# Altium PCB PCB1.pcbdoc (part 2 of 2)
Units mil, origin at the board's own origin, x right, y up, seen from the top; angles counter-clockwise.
Board outline 3937 x 1574.8 mil, 4 copper layers (Top Layer, Inner1, Inner2, Bottom Layer), stack 62.3 mil thick; 79 components, 49 nets, 279 pads, 327 vias.
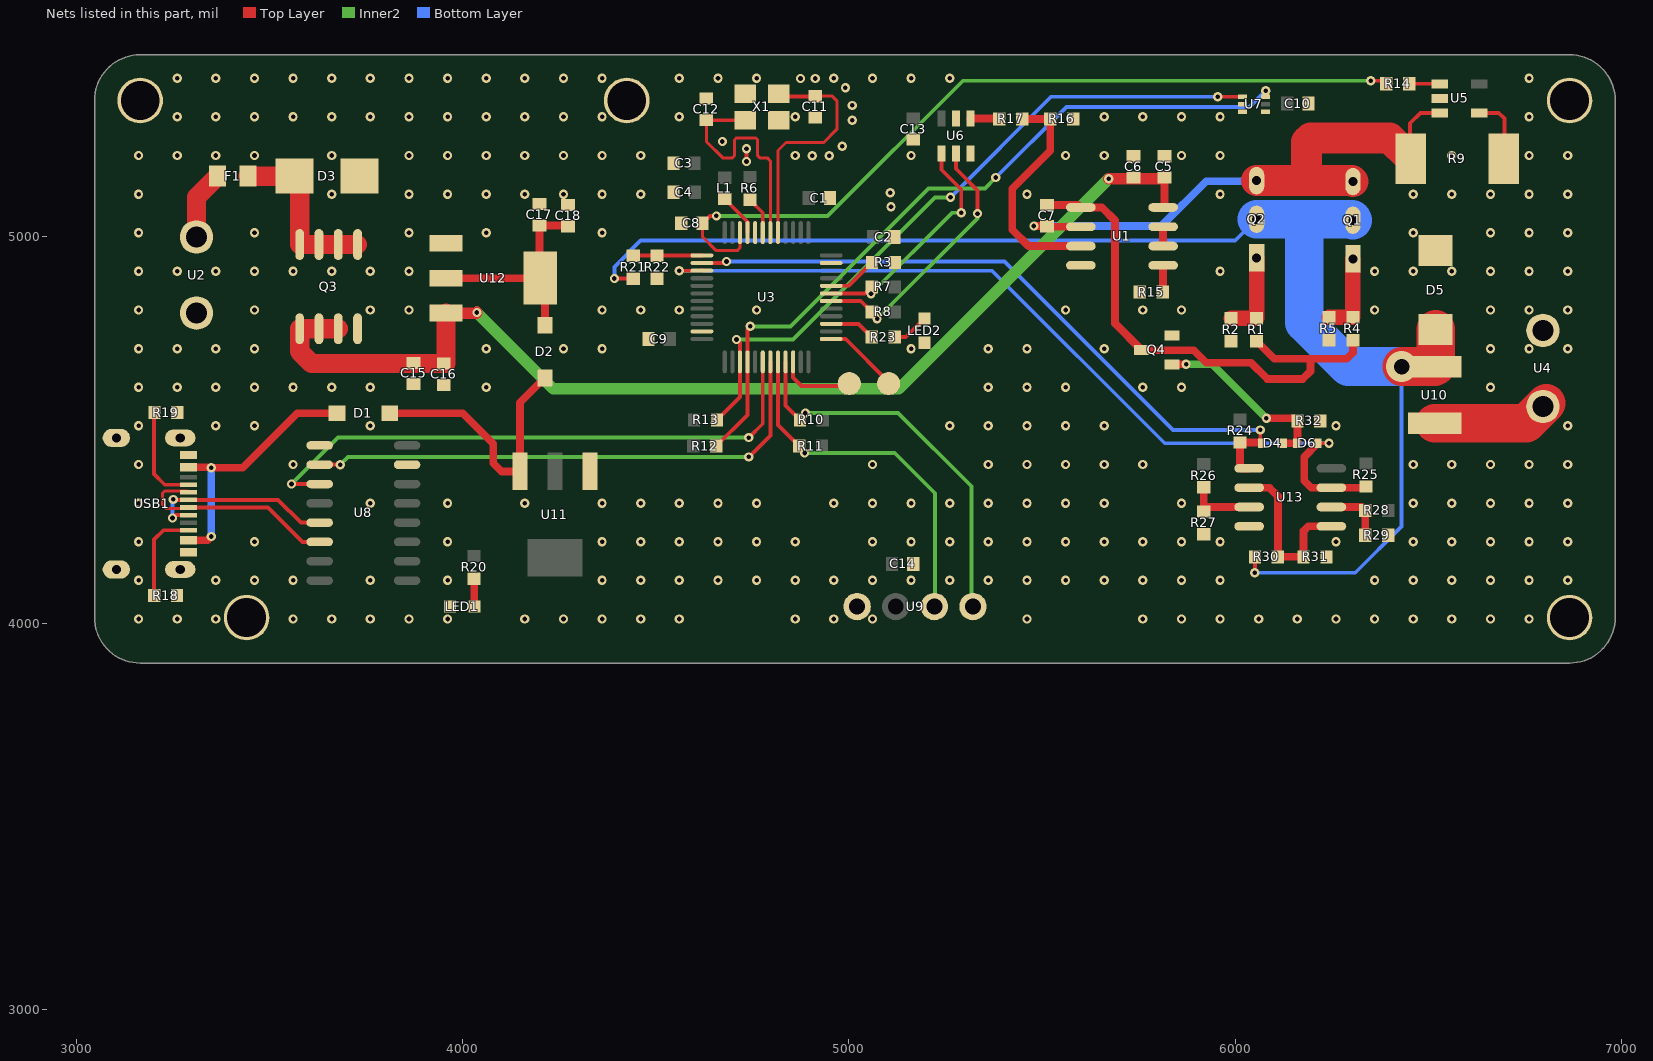
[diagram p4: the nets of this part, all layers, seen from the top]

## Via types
v1: diameter 24, hole 12, Top Layer to Bottom Layer, 326 vias
v2: diameter 80, hole 40, Top Layer to Bottom Layer, 1 vias

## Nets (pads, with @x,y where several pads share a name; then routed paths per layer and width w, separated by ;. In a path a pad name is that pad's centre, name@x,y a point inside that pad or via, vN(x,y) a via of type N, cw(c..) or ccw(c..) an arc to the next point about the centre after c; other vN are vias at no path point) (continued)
$1N126: L1.2 U3.9 | length 111.3
  Top Layer w10: L1.2@4678.6,5097.9 4737.5,5039 U3.9@4737.5,5011
$1N164: R6.2 U3.7 | length 98.6
  Top Layer w10: R6.2@4743.6,5095.8 4776.9,5062.5 U3.7@4776.9,5011
$1N212: R15.2 U1.5 | length 69.4
  Top Layer w20: R15.2@5812.5,4857.1 5813.4,4858 U1.5@5813.4,4926.1
$1N219: Q1.1 R4.2 R5.1 | length 213.2
  Top Layer w40: R5.1@6242.9,4791.9 R4.2@6304.9,4791.9 Q1.1@6304.9,4943.1
$1N221: Q2.1 R1.2 R2.1 | length 222.3
  Top Layer w40: R2.1@5989.6,4789.2 R1.2@6055.6,4789.2 Q2.1@6055.6,4945.5
$1N267: R14.2 U5.1 | length 79.4
  Top Layer w10: R14.2@6450.5,5396.2 6529.1,5396.2 U5.1@6529.7,5395.6
$1N317: C17.2 C18.2 D2.2 U12.2 U12.4 | length 582.8
  Top Layer w20: U12.2@3956.9,4893.1 U12.4@4200.9,4893.1 ; D2.2@4212.9,4771.4 4212.9,4881.1 U12.4@4200.9,4893.1 ; C18.2@4272.9,5027.6 4270.9,5029.6 C17.2@4198.9,5029.6 4198.9,4895.1 U12.4@4200.9,4893.1
$1N320: LED1.2 R20.2 | length 71.9
  Top Layer w20: R20.2@4029.8,4114.6 4029.8,4043.5 LED1.2@4030.4,4042.9
$1N345: R23.1 U3.39 | length 119
  Top Layer w10: U3.39@4954.1,4774.7 5024.7,4774.7 R23.1@5058.9,4740.5
$1N346: LED2.2 R23.2 | length 97.6
  Top Layer w10: R23.2@5118.3,4740.5 5147.3,4740.5 LED2.2@5195.8,4789
$1N390: R28.1 R29.1 U13.6 | length 155.6
  Top Layer w20: U13.6@6249.2,4300.5 6328.1,4300.5 R28.1@6337.1,4291.5 R29.1@6337.1,4227.5
$1N398: R26.2 R27.2 U13.3 | length 184.9
  Top Layer w20: R26.2@5918.7,4351.8 R27.2@5918.7,4289.1 5930.1,4300.5 U13.3@6036.2,4300.5
+5V: D1.1 D2.1 U11.3 | length 698
  Top Layer w20: D1.1@3811.2,4543.1 4000,4543.1 4078.9,4464.2 4078.9,4414.2 4100.9,4392.2 4147.8,4392.2 U11.3@4148.3,4392.7 4148.3,4570.3 D2.1@4212.9,4634.8
+12V: C5.2 C6.2 C15.2 C16.2 Q3.1 Q3.2 Q3.3 U1.8 U12.3 | length 2929.6
  Top Layer w20: U1.8@5813.4,5076.1 5816.9,5079.6 C5.2@5816.9,5153.6
  Top Layer w30: U12.3@3956.9,4802.6 4035.2,4802.6 v1(4036.9,4804.2) ; v1(5672.9,5150.2) 5813.5,5150.2 C5.2@5816.9,5153.6
  Top Layer w50: Q3.3@3677.9,4762.2 Q3.2@3627.9,4762.2 Q3.1@3577.9,4762.2 3577.9,4703.2 3608.9,4672.2 3956.9,4672.2 U12.3@3956.9,4802.6
  Inner2 w30: v1(4036.9,4804.2) 4234.9,4606.2 5128.9,4606.2 v1(5672.9,5150.2)
ADC: C8.2 R14.1 U3.10 | length 2115.6
  Top Layer w8: C8.2@4620.9,5035.2 4620.9,5000.2 4656.9,4964.2 4710.9,4964.2 4717.8,4971.2 U3.10@4717.8,5011
  Top Layer w10: C8.2@4621.1,5035.5 4639.9,5054.2 v1(4656.9,5054.2) ; v1(6350.9,5404.2) 6383.2,5404.2 R14.1@6391.2,5396.2
  Inner2 w10: v1(4656.9,5054.2) 4944.9,5054.2 5294.9,5404.2 v1(6350.9,5404.2)
BOOT0: R3.1 U3.44 | length 131
  Top Layer w10: U3.44@4954.1,4873.2 4999,4873.2 R3.1@5059.9,4934
DAC_OUT: R17.1 U6.1 | length 75.5
  Top Layer w20: U6.1@5314.3,5306.4 5388,5306.4 R17.1@5389.2,5305.1
FAULT_KILL: D4.2 D6.2 Q4.1 R32.2 | length 479.5
  Top Layer w20: Q4.1@5836.3,4669.7 5836.7,4670.2 v1(5872.9,4670.2) ; v1(6080.9,4530.2) 6154.3,4530.2 R32.2@6161.1,4523.5 6161.1,4467.4 D6.2@6159.2,4465.5 D4.2@6124.3,4465.5
  Inner2 w20: v1(5872.9,4670.2) 5940.9,4670.2 v1(6080.9,4530.2)
GATE_CTRL: C7.2 Q4.3 R1.1 R4.1 U1.1 | length 1373.3
  Top Layer w20: C7.2@5512.9,5082.7 5593.8,5082.7 U1.1@5600.4,5076.1 5600.5,5076.2 5654.9,5076.2 5688.9,5042.2 5688.9,4775.8 Q4.3@5757.5,4707.1 5758.4,4706.2 5892.9,4706.2 5924.9,4674.2 6040.9,4674.2 6082.9,4632.2 6174.9,4632.2 6194.9,4652.2 6194.9,4681.6 6192.3,4684.2 ; R1.1@6055.6,4729.8 6101.2,4684.2 6192.3,4684.2 ; R4.1@6304.9,4732.6 6304.9,4700.2 6288.9,4684.2 6192.3,4684.2
GND: C1.2 C2.2 C3.1 C4.1 C5.1 C6.1 C8.1 C9.2 C10.1 C11.2 C12.1 C13.1 C14.2 C15.1 C16.1 C17.1 C18.1 D3.2 D5.2 LED1.1 LED2.1 pad.1@3165,5352.9 pad.1@3440.6,4014.3 pad.1@4424.8,5352.9 pad.1@6865.8,4014.3 pad.1@6865.8,5352.9 Q3.4 Q4.2 R2.2 R3.2 R5.2 R9.2 R15.1 R16.2 R18.1 R19.1 R22.2 R27.1 R29.2 R31.2 R32.1 U1.4 U2.2 U3.8 U3.23 U3.47 U4.2 U5.2 U5.4 U6.2 U6.6 U7.2 U7.3 U7.4 U8.1 U8.15 U9.1 U11.1 U12.1 U13.4 USB1.13 USB1.14 USB1.A1B12 USB1.B1A12 X1.2 X1.4 | length 208.6
  Top Layer w10: v1(4734.9,5195) v1(4734.9,5228.2) ; U5.4@6632.1,5320.8 6682.3,5320.8 6696.9,5306.2 6696.9,5203.5 R9.2@6695.6,5202.2
  other v1: 3161,4010.6 3261,4010.6 3361,4010.6 3561,4010.6 3661,4010.6 3761,4010.6 3861,4010.6 3961,4010.6 4161,4010.6 4261,4010.6 4361,4010.6 4461,4010.6 4561,4010.6 4861,4010.6 4961,4010.6 5061,4010.6 5461,4010.6 5761,4010.6 5861,4010.6 5961,4010.6 6061,4010.6 6161,4010.6 6261,4010.6 6361,4010.6 6461,4010.6 6561,4010.6 6661,4010.6 6761,4010.6 3161,4110.6 3361,4110.6 3461,4110.6 3561,4110.6 3761,4110.6 3961,4110.6 4361,4110.6 4461,4110.6 4561,4110.6 4661,4110.6 4761,4110.6 4861,4110.6 4961,4110.6 5061,4110.6 5161,4110.6 5261,4110.6 5361,4110.6 5461,4110.6 5561,4110.6 5661,4110.6 5761,4110.6 5861,4110.6 5961,4110.6 6361,4110.6 6461,4110.6 6561,4110.6 6661,4110.6 6761,4110.6 6861,4110.6 3161,4210.6 3461,4210.6 3961,4210.6 4361,4210.6 4461,4210.6 4561,4210.6 4661,4210.6 4761,4210.6 4861,4210.6 5061,4210.6 5161,4210.6 5261,4210.6 5361,4210.6 5461,4210.6 5561,4210.6 5661,4210.6 5761,4210.6 5861,4210.6 5961,4210.6 6261,4210.6 6461,4210.6 6561,4210.6 6661,4210.6 6761,4210.6 6861,4210.6 3161,4310.6 3761,4310.6 3961,4310.6 4161,4310.6 4361,4310.6 4461,4310.6 4561,4310.6 4661,4310.6 4761,4310.6 4961,4310.6 5061,4310.6 5161,4310.6 5261,4310.6 5361,4310.6 5461,4310.6 5561,4310.6 5661,4310.6 5861,4310.6 6461,4310.6 6561,4310.6 6661,4310.6 6761,4310.6 6861,4310.6 3161,4410.6 3561,4410.6 5061,4410.6 5361,4410.6 5461,4410.6 5561,4410.6 5661,4410.6 5761,4410.6 6461,4410.6 6561,4410.6 6661,4410.6 6761,4410.6 6861,4410.6 3161,4510.6 3361,4510.6 3461,4510.6 3761,4510.6 5261,4510.6 5361,4510.6 5461,4510.6 5561,4510.6 5661,4510.6 6261,4510.6 6861,4510.6 3161,4610.6 3261,4610.6 3361,4610.6 3461,4610.6 3561,4610.6 3661,4610.6 3761,4610.6 4061,4610.6 5361,4610.6 5461,4610.6 5561,4610.6 5761,4610.6 5861,4610.6 6661,4610.6 3161,4710.6 3261,4710.6 3361,4710.6 3461,4710.6 4061,4710.6 4261,4710.6 4361,4710.6 5161,4710.6 5361,4710.6 5461,4710.6 5661,4710.6 6661,4710.6 6761,4710.6 6861,4710.6 3161,4810.6 3461,4810.6 3761,4810.6 3861,4810.6 4361,4810.6 4461,4810.6 4561,4810.6 4761,4810.6 5561,4810.6 5761,4810.6 5861,4810.6 6361,4810.6 6661,4810.6 6761,4810.6 6861,4810.6 3161,4910.6 3261,4910.6 3361,4910.6 3461,4910.6 3561,4910.6 3661,4910.6 3761,4910.6 3861,4910.6 5961,4910.6 6361,4910.6 6461,4910.6 6561,4910.6 6661,4910.6 6761,4910.6 6861,4910.6 3161,5010.6 3461,5010.6 3861,5010.6 4061,5010.6 4361,5010.6 6461,5010.6 6661,5010.6 6761,5010.6 6861,5010.6 5108.9,5078.2 3161,5110.6 3661,5110.6 3861,5110.6 3961,5110.6 4061,5110.6 4161,5110.6 4261,5110.6 4361,5110.6 4461,5110.6 5461,5110.6 5961,5110.6 6461,5110.6 6561,5110.6 6661,5110.6 6761,5110.6 6861,5110.6 5106.9,5114.2 4904.9,5210.2 4949,5210.2 3161,5210.6 3261,5210.6 3361,5210.6 3461,5210.6 3661,5210.6 3861,5210.6 3961,5210.6 4061,5210.6 4161,5210.6 4261,5210.6 4361,5210.6 4461,5210.6 4861,5210.6 5161,5210.6 5561,5210.6 5661,5210.6 5861,5210.6 5961,5210.6 6561,5210.6 6761,5210.6 6861,5210.6 4982.9,5234.2 4672.5,5246.7 5008.9,5302.2 3261,5310.6 3361,5310.6 3461,5310.6 3561,5310.6 3661,5310.6 3761,5310.6 3861,5310.6 3961,5310.6 4061,5310.6 4161,5310.6 4261,5310.6 4361,5310.6 4561,5310.6 4861,5310.6 5661,5310.6 5761,5310.6 5861,5310.6 5961,5310.6 6761,5310.6 5008.9,5340.3 4990.9,5386.2 4874.8,5409.8 4912.9,5409.8 3261,5410.6 3361,5410.6 3461,5410.6 3561,5410.6 3661,5410.6 3761,5410.6 3861,5410.6 3961,5410.6 4061,5410.6 4161,5410.6 4261,5410.6 4361,5410.6 4561,5410.6 4661,5410.6 4761,5410.6 4961,5410.6 5061,5410.6 5161,5410.6 5261,5410.6 6761,5410.6
I2C1_SCL: R8.1 U3.42 U6.5 | length 675.5
  Top Layer w10: U3.42@4954.1,4833.8 5030.6,4833.8 R8.1@5058.9,4805.5 ; U6.5@5276.9,5215.9 5276.9,5176.2 5332.9,5120.2 v1(5332.9,5060.2)
  Inner2 w10: v1(5073,4787.8) 5332.9,5047.6 v1(5332.9,5060.2)
I2C1_SDA: R7.1 U3.43 U6.4 | length 607.2
  Top Layer w10: U3.43@4954.1,4853.5 5041.9,4853.5 R7.1@5058.9,4870.5 ; U6.4@5239.5,5215.9 5239.5,5173.6 5290.9,5122.2 v1(5290.9,5062.2)
  Inner2 w10: v1(5057.3,4852.8) 5266.7,5062.2 v1(5290.9,5062.2)
I2C2_SCL: R11.1 U3.32 U9.3 | length 915.7
  Top Layer w10: U3.32@4816.3,4676.3 4816.3,4513.2 R11.1@4871.2,4458.2
  Inner2 w10: v1(4885.3,4440.5) 5118.6,4440.5 5222.9,4336.2 5222.9,4044.5 U9.3@5221.2,4042.8
I2C2_SDA: R10.1 U3.33 U9.4 | length 986.8
  Top Layer w10: U3.33@4836,4676.3 4836,4563.5 R10.1@4873.2,4526.2
  Inner2 w10: v1(4887.3,4543.9) 5127.2,4543.9 5316.9,4354.2 5316.9,4047.1 U9.4@5321.2,4042.8
I_SET: R16.1 R17.2 U1.3 | length 595.2
  Top Layer w20: R17.2@5448.5,5305.1 R16.1@5521.2,5305.1 5521.2,5222.6 5422.9,5124.2 5422.9,5018.2 5464.9,4976.2 5600.3,4976.2 U1.3@5600.4,4976.1
ISENSE: C7.1 Q1.3 Q2.3 R9.1 U1.2 U5.3 | length 1581.1
  Top Layer w10: R9.1@6452.9,5203.5 6452.9,5294.2 6479.5,5320.8 U5.3@6529.7,5320.8
  Top Layer w20: v1(5478.9,5028.2) 5512.2,5028.2 C7.1@5512.9,5027.6 5514.3,5026.1 U1.2@5600.4,5026.1
  Top Layer w80: Q2.3@6055.6,5145.5 6165.2,5145.5 ; Q1.3@6304.9,5143.1 6302.5,5145.5 6165.2,5145.5 ; R9.1@6454.2,5202.2 6452.9,5203.5 6400.2,5256.2 6194.9,5256.2 6184.9,5246.2 6184.9,5165.2 6165.2,5145.5
  Bottom Layer w20: v1(5478.9,5028.2) 5808.9,5028.2 5924.9,5144.2 6054.3,5144.2 Q2.3@6055.6,5145.5
LOAD+: D5.1 Q1.2 Q2.2 R21.1 R30.1 U10.2 | length 3665.5
  Top Layer w10: v1(4392.9,4892.2) 4441.2,4892.2 R21.1@4441.6,4891.8 ; v1(6050.9,4130.2) 6050.9,4171.3 R30.1@6051.1,4171.5
  Top Layer w100: v2(6430.9,4664.2) 6515.9,4664.2 U10.2@6516.9,4663.2 6518.9,4665.2 D5.1@6518.9,4760.2
  Bottom Layer w10: v1(4392.9,4892.2) 4392.9,4922.2 4460.9,4990.2 6000.3,4990.2 Q2.2@6055.6,5045.5 ; v1(6050.9,4130.2) 6310.9,4130.2 6430.9,4250.2 v2(6430.9,4664.2)
  Bottom Layer w100: Q2.2@6055.6,5045.5 6302.5,5045.5 Q1.2@6304.9,5043.1 ; 6178.9,5032.2 6178.9,4778.2 6292.9,4664.2 v2(6430.9,4664.2)
LOAD_CMP_SENSE: R30.2 R31.1 U13.2 U13.5 | length 451.6
  Top Layer w20: U13.2@6036.2,4350.5 6088.6,4350.5 6110.9,4328.2 6110.9,4172 R30.2@6110.4,4171.5 R31.1@6177.1,4171.5 6177.1,4238.4 6189.1,4250.5 U13.5@6249.2,4250.5
LOAD_IN+: U4.1 U10.1 | length 310.6
  Top Layer w100: U10.1@6516.9,4517.2 6753.4,4517.2 U4.1@6805.8,4569.6
LOAD_VOLT_ADC: R21.2 R22.1 U3.13 | length 178.1
  Top Layer w10: R21.2@4441.6,4951.1 4442.4,4951.9 U3.13@4619.4,4951.9
OP2_BUF_OUT: U1.6 U1.7 | length 50
  Top Layer w20: U1.6@5813.4,4976.1 U1.7@5813.4,5026.1
OSC_IN: C11.1 U3.5 X1.3 | length 620.5
  Top Layer w8: U3.5@4816.3,5011 4816.3,5223.6 4836.9,5244.2 4934.9,5244.2 4968.9,5278.2 4968.9,5352.2 4956.9,5364.2 4913.3,5364.2 C11.1@4912.9,5363.8
  Top Layer w10: X1.3@4818.2,5370.7 4825.1,5363.8 C11.1@4912.9,5363.8
OSC_OUT: C12.2 U3.6 X1.1 | length 619.3
  Top Layer w8: C12.2@4630.9,5302.7 4630.9,5246.7 4673,5204.5 4698,5204.5 4703.7,5210.2 4703.7,5250.6 4709.3,5256.2 4758,5256.2 4763.7,5250.6 4763.7,5210.2 4769.3,5204.5 4788.6,5204.5 4796.6,5196.5 U3.6@4796.6,5011
  Top Layer w10: C12.2@4630.9,5302.7 4631.8,5301.8 X1.1@4731.6,5301.8
OV_FAULT: D6.1 R25.1 U3.15 U13.7 | length 2235
  Top Layer w10: v1(4560.9,4912.2) 4619.1,4912.2 U3.15@4619.4,4912.5 ; D6.1@6214.3,4465.5 v1(6242.9,4465.5)
  Top Layer w20: D6.1@6214.3,4465.5 6178.9,4430.1 6178.9,4368.2 6196.9,4350.2 6249,4350.2 U13.7@6249.2,4350.5 6335.4,4350.5 R25.1@6338.7,4353.8
  Bottom Layer w10: v1(4560.9,4912.2) 5370.9,4912.2 5817.6,4465.5 v1(6242.9,4465.5)
REV_FAULT: D4.1 R24.1 U3.14 U13.1 | length 1804.2
  Top Layer w10: U3.14@4619.4,4932.2 4678.9,4932.2 v1(4682.9,4936.2) ; D4.1@6064.9,4469.7 v1(6064.9,4500.2)
  Top Layer w20: U13.1@6036.2,4400.5 6016.6,4400.5 6012.7,4404.4 R24.1@6012.7,4467.8 6066.8,4467.8 D4.1@6069.2,4465.5
  Bottom Layer w10: v1(4682.9,4936.2) 5402.9,4936.2 5838.9,4500.2 v1(6064.9,4500.2)
SW_SCL: R13.1 U3.27 U7.1 | length 1806.7
  Top Layer w10: R13.1@4658.5,4526.2 4717.8,4585.5 U3.27@4717.8,4676.3 4717.8,4725.3 v1(4708.9,4734.2) ; v1(5954.9,5362.7) U7.1@6019,5362.7
  Inner2 w10: v1(4708.9,4734.2) 4854.9,4734.2 5222.9,5102.2 v1(5262.9,5102.2)
  Bottom Layer w10: v1(5262.9,5102.2) 5523.4,5362.7 v1(5954.9,5362.7)
SW_SDA: R12.1 U3.28 U7.6 | length 1949.1
  Top Layer w10: R12.1@4656.5,4458.2 4737.5,4539.2 U3.28@4737.5,4676.3 4737.5,4760.9 v1(4744.9,4768.2) ; U7.6@6078.1,5362.7 6078.9,5363.5 v1(6078.9,5378.2)
  Inner2 w10: v1(4744.9,4768.2) 4848.9,4768.2 5205.9,5125.2 5351.9,5125.2 v1(5380.3,5153.6)
  Bottom Layer w10: v1(5380.3,5153.6) 5562.9,5336.2 6036.9,5336.2 v1(6078.9,5378.2)
SWCLK: pad.1@5102.9,4620.2 U3.37 | length 198.9
  Top Layer w10: U3.37@4954.1,4735.4 4991.7,4735.4 5102.9,4624.2 pad.1@5102.9,4620.2
SWDIO: pad.1@5000.9,4620.2 U3.34 | length 197.4
  Top Layer w10: U3.34@4855.6,4676.3 4855.6,4635.5 4876.9,4614.2 4994.9,4614.2 pad.1@5000.9,4620.2
USART1_RX: U3.31 U8.2 | length 1388.6
  Top Layer w10: U8.2@3629.8,4410.1 3629.9,4410.2 v1(3682.9,4410.2) ; v1(4740.9,4430.2) 4796.6,4485.9 U3.31@4796.6,4676.3
  Inner2 w10: v1(3682.9,4410.2) 3702.9,4430.2 v1(4740.9,4430.2)
USART1_TX: U3.30 U8.3 | length 1517.7
  Top Layer w10: v1(3556.9,4360.2) 3629.7,4360.2 U8.3@3629.8,4360.1 ; v1(4740.9,4480.2) 4776.9,4516.2 U3.30@4776.9,4676.3
  Inner2 w10: v1(3556.9,4360.2) 3676.9,4480.2 v1(4740.9,4480.2)
USB_CC1: R19.2 USB1.A5 | length 260.4
  Top Layer w10: R19.2@3201.9,4545.1 3200.9,4544.1 3200.9,4386.2 3228.8,4358.3 USB1.A5@3290.4,4358.3
USB_CC2: R18.2 USB1.B5 | length 244.6
  Top Layer w10: R18.2@3201.2,4071.1 3200.9,4071.5 3200.9,4216.2 3224.9,4240.2 USB1.B5@3290.4,4240.2
USB_DN: U8.6 USB1.A7 USB1.B7 | length 550.7
  Top Layer w8: USB1.A7@3290.4,4299.3 3287.3,4296.2 3232.9,4296.2 3222.9,4306.2 3222.9,4336.2 3228.9,4342.2 3286.8,4342.2 USB1.B7@3290.4,4338.7
  Top Layer w10: USB1.A7@3290.4,4299.3 3495.8,4299.3 3585,4210.1 U8.6@3629.8,4210.1
USB_DP: U8.5 USB1.A6 USB1.B6 | length 497.2
  Top Layer w10: v1(3248.9,4272.2) 3256.3,4279.6 USB1.B6@3290.4,4279.6 ; v1(3250.9,4320.2) 3252.1,4319 USB1.A6@3290.4,4319 3522.1,4319 3581,4260.1 U8.5@3629.8,4260.1
  Bottom Layer w10: v1(3248.9,4272.2) 3248.9,4318.2 v1(3250.9,4320.2)
USB_VBUS: D1.2 USB1.A4B9 USB1.B4A9 | length 683.6
  Top Layer w20: USB1.B4A9@3290.4,4214.6 3339.3,4214.6 v1(3348.9,4224.2) ; USB1.A4B9@3290.4,4403.6 3347.5,4403.6 v1(3348.9,4402.2) 3430.9,4402.2 3571.8,4543.1 D1.2@3674.6,4543.1
  Bottom Layer w20: v1(3348.9,4224.2) v1(3348.9,4402.2)
VIN_12V_FUSED: D3.1 F1.2 Q3.5 Q3.6 Q3.7 Q3.8 | length 452.6
  Top Layer w50: F1.2@3444.3,5157.1 D3.1@3564.2,5157.1 3577.9,5143.5 Q3.8@3577.9,4980.1 Q3.7@3627.9,4980.1 Q3.6@3677.9,4980.1 Q3.5@3727.9,4980.1
VIN_12V_IN: F1.1 U2.1 | length 180.1
  Top Layer w50: U2.1@3310.9,4999.6 3310.9,5102.5 F1.1@3365.5,5157.1
pads on no net: U3.2 U3.3 U3.4 U3.11 U3.12 U3.16 U3.17 U3.18 U3.19 U3.20 U3.21 U3.22 U3.25 U3.26 U3.29 U3.35 U3.36 U3.38 U3.40 U3.41 U3.45 U3.46 U8.7 U8.8 U8.9 U8.10 U8.11 U8.12 U8.13 U8.14 USB1.A8 USB1.B8

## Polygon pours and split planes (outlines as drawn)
GND on Top Layer (solid, remove dead copper, pour order 2): 3165,5471.3 ccw(c3165,5353.2) 3046.9,5353.2 3046.9,4014.6 ccw(c3165,4014.6) 3165,3896.5 6865.8,3896.5 ccw(c6865.8,4014.6) 6983.9,4014.6 6983.9,5353.2 ccw(c6865.8,5353.2) 6865.8,5471.3
GND on Bottom Layer (solid, remove dead copper, pour order 2): 3165,5471.3 ccw(c3165,5353.2) 3046.9,5353.2 3046.9,4014.6 ccw(c3165,4014.6) 3165,3896.5 6865.8,3896.5 ccw(c6865.8,4014.6) 6983.9,4014.6 6983.9,5353.2 ccw(c6865.8,5353.2) 6865.8,5471.3
GND on Inner1 (solid, remove dead copper): 3165,5471.3 ccw(c3165,5353.2) 3046.9,5353.2 3046.9,4014.6 ccw(c3165,4014.6) 3165,3896.5 6865.8,3896.5 ccw(c6865.8,4014.6) 6983.9,4014.6 6983.9,5353.2 ccw(c6865.8,5353.2) 6865.8,5471.3
GND on Inner2 (solid, remove dead copper): 3165,5471.3 ccw(c3165,5353.2) 3046.9,5353.2 3046.9,4014.6 ccw(c3165,4014.6) 3165,3896.5 6865.8,3896.5 ccw(c6865.8,4014.6) 6983.9,4014.6 6983.9,5353.2 ccw(c6865.8,5353.2) 6865.8,5471.3

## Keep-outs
Board Outline Layer:
  lines w10: 6865.8,3896.5 3165,3896.5 cw(c3165,4014.6) 3046.9,4014.6 3046.9,5353.2 cw(c3165,5353.2) 3165,5471.3 6865.8,5471.3 ; 6865.8,3896.5 6865.8,3896.5 ; 6865.8,3896.5 ccw(c6865.8,4014.6) 6983.9,4014.6 ; 6865.8,5471.3 cw(c6865.8,5353.2) 6983.9,5353.2 ; 6865.8,5471.3 6865.8,5471.3 ; 6983.9,4014.6 6983.9,4014.6 ; 6983.9,4014.6 6983.9,5353.2 ; 6983.9,5353.2 6983.9,5353.2

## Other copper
Top Layer:
  drawing of 259 lines, arcs and shapes, not listed
Inner2:
  region net I2C2_SCL: 5217.9,4092.3 5227.9,4089.8 5228.1,4087.9 5228.6,4086 5229.5,4084.2 5230.6,4082.4 5231.9,4080.6 5233.5,4078.9 5236.9,4075.5 5240.4,4072.4 5243.9,4069.6 5246.8,4067.1 5248.9,4065 5195.8,4067.5 5203.9,4076 5211,4083.8 5216,4089.6 5217.4,4091.4
  region net I2C2_SDA: 5311.9,4087.6 5321.9,4094.1 5322,4093.6 5322.4,4092.8 5323.8,4090.7 5326.1,4087.9 5329,4084.6 5336.3,4077.1 5344.7,4069.3 5292,4062.8 5293.9,4065 5296.6,4067.5 5303.3,4073.5 5306.5,4076.8 5308,4078.5 5309.3,4080.3 5310.4,4082.1 5311.2,4083.9 5311.7,4085.8
  region net USART1_TX: 4724.5,4475.2 4724.5,4485.2 4726.3,4485.6 4728.6,4486.5 4730.9,4487.8 4732.9,4489.2 4732.9,4471.2 4730.9,4472.7 4728.6,4474 4726.3,4474.9
  region net USART1_RX: 4724.5,4425.2 4724.5,4435.2 4726.3,4435.6 4728.6,4436.5 4730.9,4437.8 4732.9,4439.2 4732.9,4421.2 4730.9,4422.7 4728.6,4424 4726.3,4424.9
  region net 3V3: 4881.6,5137.4 4881.6,5157.4 4883.8,5157.5 4885.9,5157.7 4889.9,5158.4 4893.4,5159.1 4896,5159.4 4896,5135.4 4893.4,5135.7 4889.9,5136.4 4885.9,5137.1 4883.8,5137.3
  region net 3V3: 4618.1,5223.1 4604,5209 4602.4,5210.4 4600.8,5211.8 4597.4,5214.1 4594.5,5216.1 4592.4,5217.7 4609.4,5234.7 4611,5232.6 4613,5229.7 4615.3,5226.3 4616.7,5224.7
  region net USART1_TX: 3564.9,4375.3 3572,4368.2 3570.9,4366.7 3570,4364.5 3569.2,4361.9 3568.9,4359.5 3556.1,4372.2 3558.6,4372.6 3561.1,4373.3 3563.4,4374.3
  region net USART1_RX: 3690.9,4425.3 3698,4418.2 3696.9,4416.7 3696,4414.5 3695.2,4411.9 3694.9,4409.5 3682.1,4422.2 3684.6,4422.6 3687.1,4423.3 3689.4,4424.3
  region net 3V3: 6056.7,4594.2 6063.8,4601.3 6065.3,4600.3 6067.6,4599.3 6070.1,4598.6 6072.6,4598.2 6059.8,4585.5 6059.5,4587.9 6058.7,4590.5 6057.8,4592.7
  region net 3V3: 6086.2,4596.2 6086.2,4576.2 6084.1,4576.1 6082,4575.9 6078,4575.2 6074.5,4574.5 6071.8,4574.2 6071.8,4598.2 6074.5,4597.9 6078,4597.2 6082,4596.5 6084.1,4596.3
  region net 3V3: 6126.9,5291.1 6119.8,5298.2 6120.8,5299.7 6121.8,5302 6122.5,5304.5 6122.9,5307 6135.6,5294.2 6133.2,5293.9 6130.6,5293.1 6128.4,5292.2
  region net 3V3: 6151.2,5311.2 6151.2,5301.2 6149.4,5300.9 6147.2,5300 6144.8,5298.7 6142.8,5297.2 6142.8,5315.2 6144.8,5313.8 6147.2,5312.5 6149.4,5311.6
  region net 3V3: 6679.9,5377.9 6669.9,5377.9 6669.5,5379.7 6668.6,5381.9 6667.3,5384.3 6665.9,5386.3 6683.9,5386.3 6682.4,5384.3 6681.1,5381.9 6680.2,5379.7
  region net FAULT_KILL: 6063.6,4533.3 6077.8,4547.5 6079.4,4546 6081,4544.7 6084.3,4542.3 6087.3,4540.4 6089.4,4538.7 6072.4,4521.7 6070.7,4523.8 6068.8,4526.8 6066.4,4530.1 6065.1,4531.8
  region net FAULT_KILL: 5887.3,4680.2 5887.3,4660.2 5885.1,4660.1 5883,4659.9 5879,4659.2 5875.6,4658.5 5872.9,4658.2 5872.9,4682.2 5875.6,4681.9 5879,4681.2 5883,4680.5 5885.1,4680.3
  region net ADC: 4673.2,5059.2 4673.2,5049.2 4671.4,5048.9 4669.2,5048 4666.8,5046.7 4664.8,5045.2 4664.8,5063.2 4666.8,5061.8 4669.2,5060.5 4671.4,5059.6
  region net ADC: 6334.5,5399.2 6334.5,5409.2 6336.3,5409.6 6338.6,5410.5 6340.9,5411.8 6342.9,5413.2 6342.9,5395.2 6340.9,5396.7 6338.6,5398 6336.3,5398.9
  region net SW_SCL: 5246.5,5097.2 5246.5,5107.2 5248.3,5107.6 5250.6,5108.5 5252.9,5109.8 5254.9,5111.2 5254.9,5093.2 5252.9,5094.7 5250.6,5096 5248.3,5096.9
  region net SW_SCL: 4725.2,4739.2 4725.2,4729.2 4723.4,4728.9 4721.2,4728 4718.8,4726.7 4716.8,4725.2 4716.8,4743.2 4718.8,4741.8 4721.2,4740.5 4723.4,4739.6
  region net SW_SDA: 5372.3,5138.5 5365.2,5145.6 5366.2,5147.1 5367.2,5149.4 5367.9,5151.9 5368.3,5154.4 5381,5141.6 5378.6,5141.3 5376,5140.5 5373.8,5139.6
  region net SW_SDA: 4761.2,4773.2 4761.2,4763.2 4759.4,4762.9 4757.2,4762 4754.8,4760.7 4752.8,4759.2 4752.8,4777.2 4754.8,4775.8 4757.2,4774.5 4759.4,4773.6
  region net I2C1_SDA: 5065.3,4867.9 5072.4,4860.8 5071.4,4859.3 5070.4,4857 5069.6,4854.5 5069.3,4852 5056.5,4864.7 5059,4865.1 5061.5,4865.9 5063.8,4866.8
  region net I2C1_SCL: 5081.1,4802.9 5088.1,4795.8 5087.1,4794.3 5086.1,4792 5085.4,4789.5 5085,4787 5072.3,4799.7 5074.7,4800.1 5077.3,4800.9 5079.5,4801.8
  region net I2C1_SDA: 5274.5,5057.2 5274.5,5067.2 5276.3,5067.6 5278.6,5068.5 5280.9,5069.8 5282.9,5071.2 5282.9,5053.2 5280.9,5054.7 5278.6,5056 5276.3,5056.9
  region net I2C1_SCL: 5337.9,5047.6 5327.9,5047.6 5323.9,5052.3 5341.9,5052.3
  region net I2C2_SDA: 4903.7,4548.9 4903.7,4538.9 4901.9,4538.6 4899.6,4537.7 4897.3,4536.4 4895.3,4534.9 4895.3,4552.9 4897.3,4551.5 4899.6,4550.2 4901.9,4549.3
  region net I2C2_SCL: 4901.7,4445.5 4901.7,4435.5 4899.9,4435.2 4897.6,4434.3 4895.3,4433 4893.3,4431.5 4893.3,4449.5 4895.3,4448 4897.6,4446.8 4899.9,4445.8
  region net 3V3: 6328.9,4482.6 6348.9,4482.6 6349,4480.5 6349.2,4478.4 6349.9,4474.4 6350.6,4470.9 6350.9,4468.2 6326.9,4468.2 6327.2,4470.9 6327.9,4474.4 6328.6,4478.4 6328.8,4480.5
Bottom Layer:
  region net LOAD+: 6026.7,5009.6 6030.6,5027.6 6031.6,5028.8 6032.5,5030.4 6033.4,5032.4 6034.2,5034.5 6034.9,5036.8 6035.4,5039.1 6035.8,5041.4 6035.9,5043.5 6042.7,5014.8 6042.1,5015.3 6041.4,5015.5 6039.7,5015.8 6037.7,5015.6 6035.6,5015.1 6033.3,5014.2 6031,5012.9 6028.8,5011.4
  region net ISENSE: 6005.9,5134.2 6005.9,5154.2 6011.5,5154.4 6016.9,5154.8 6022,5155.5 6026.5,5156.4 6030.3,5157.5 6033.3,5158.7 6034.4,5159.3 6035.2,5159.9 6035.7,5160.6 6035.9,5161.3 6035.9,5129.8 6035.7,5130.2 6035.2,5130.6 6033.3,5131.4 6030.3,5132.1 6026.5,5132.8 6022,5133.4 6016.9,5133.8 6011.5,5134.1
  region net ISENSE: 5493.3,5038.2 5493.3,5018.2 5491.1,5018.1 5489,5017.9 5485,5017.2 5481.6,5016.5 5478.9,5016.2 5478.9,5040.2 5481.6,5039.9 5485,5039.2 5489,5038.5 5491.1,5038.3
  region net LOAD+: 4387.9,4908.6 4397.9,4908.6 4398.2,4906.8 4399.1,4904.5 4400.4,4902.2 4401.9,4900.2 4383.9,4900.2 4385.3,4902.2 4386.6,4904.5 4387.5,4906.8
  region net USB_DP: 3243.9,4288.6 3253.9,4288.6 3254.2,4286.8 3255.1,4284.5 3256.4,4282.2 3257.9,4280.2 3239.9,4280.2 3241.3,4282.2 3242.6,4284.5 3243.5,4286.8
  region net USB_DP: 3253.9,4302.5 3243.9,4305.5 3243.6,4307.1 3242.9,4309.3 3241.9,4311.7 3240.7,4313.9 3258.4,4310.9 3256.8,4309.1 3255.3,4306.9 3254.3,4304.5 3254,4303.4
  region net USB_VBUS: 3338.9,4238.6 3358.9,4238.6 3359,4236.5 3359.2,4234.4 3359.9,4230.4 3360.6,4226.9 3360.9,4224.2 3336.9,4224.2 3337.2,4226.9 3337.9,4230.4 3338.6,4234.4 3338.8,4236.5
  region net USB_VBUS: 3358.9,4387.8 3338.9,4387.8 3338.8,4390 3338.6,4392.1 3337.9,4396.1 3337.2,4399.5 3336.9,4402.2 3360.9,4402.2 3360.6,4399.5 3359.9,4396.1 3359.2,4392.1 3359,4390
  region net 3V3: 3716.1,4279.1 3702,4265 3700.4,4266.4 3698.8,4267.8 3695.4,4270.1 3692.5,4272.1 3690.4,4273.7 3707.4,4290.7 3709,4288.6 3711,4285.7 3713.3,4282.3 3714.7,4280.7
  region net 3V3: 3966.5,4164.2 3966.5,4184.2 3968.6,4184.3 3970.7,4184.5 3974.7,4185.2 3978.2,4185.9 3980.9,4186.2 3980.9,4162.2 3978.2,4162.5 3974.7,4163.2 3970.7,4163.9 3968.6,4164.1
  region net OV_FAULT: 6226.5,4460.5 6226.5,4470.5 6228.3,4470.8 6230.6,4471.7 6232.9,4473 6234.9,4474.5 6234.9,4456.4 6232.9,4457.9 6230.6,4459.2 6228.3,4460.1
  region net OV_FAULT: 4577.2,4917.2 4577.2,4907.2 4575.4,4906.9 4573.2,4906 4570.8,4904.7 4568.8,4903.2 4568.8,4921.2 4570.8,4919.8 4573.2,4918.5 4575.4,4917.6
  region net REV_FAULT: 4699.2,4941.2 4699.2,4931.2 4697.4,4930.9 4695.2,4930 4692.8,4928.7 4690.8,4927.2 4690.8,4945.2 4692.8,4943.8 4695.2,4942.5 4697.4,4941.6
  region net REV_FAULT: 6048.5,4495.2 6048.5,4505.2 6050.3,4505.6 6052.6,4506.5 6054.9,4507.8 6056.9,4509.2 6056.9,4491.2 6054.9,4492.7 6052.6,4494 6050.3,4494.9
  region net SW_SCL: 5938.5,5357.7 5938.5,5367.7 5940.3,5368 5942.6,5368.9 5944.9,5370.2 5946.9,5371.7 5946.9,5353.7 5944.9,5355.2 5942.6,5356.4 5940.3,5357.3
  region net SW_SCL: 5270.9,5117.3 5278,5110.2 5276.9,5108.7 5276,5106.5 5275.2,5103.9 5274.9,5101.5 5262.1,5114.2 5264.6,5114.6 5267.1,5115.3 5269.4,5116.3
  region net SW_SDA: 6070.9,5363.1 6063.8,5370.2 6064.8,5371.7 6065.8,5374 6066.5,5376.5 6066.9,5379 6079.6,5366.2 6077.2,5365.9 6074.6,5365.1 6072.4,5364.2
  region net SW_SDA: 5388.3,5168.7 5395.4,5161.7 5394.4,5160.1 5393.4,5157.9 5392.7,5155.3 5392.3,5152.9 5379.5,5165.6 5382,5166 5384.5,5166.7 5386.8,5167.7
  region net LOAD+: 6435.9,4609.8 6425.9,4609.8 6425.7,4611.9 6425,4613.9 6424,4616 6422.7,4618.1 6421.1,4620.1 6419.3,4622.1 6415.2,4625.8 6411,4629.4 6406.9,4632.6 6403.4,4635.4 6400.9,4637.8 6460.9,4637.8 6458.4,4635.4 6454.9,4632.6 6450.8,4629.4 6446.5,4625.8 6442.5,4622.1 6440.7,4620.1 6439.1,4618.1 6437.8,4616 6436.8,4613.9 6436.1,4611.9
  region net LOAD+: 6067.2,4135.2 6067.2,4125.2 6065.4,4124.9 6063.2,4124 6060.8,4122.7 6058.8,4121.2 6058.8,4139.2 6060.8,4137.8 6063.2,4136.5 6065.4,4135.6
  region net LOAD+: 6435.9,4527.4 6425.9,4514.2 6425.5,4526 6424.4,4537.7 6422.5,4549.3 6419.8,4560.8 6416.4,4572 6412.3,4583.1 6407.5,4593.8 6402,4604.2 6395.9,4614.2 6464.7,4627.4 6458.8,4617.3 6453.5,4606.9 6448.9,4596.1 6445,4585.1 6441.7,4573.8 6439.2,4562.4 6437.3,4550.8 6436.2,4539.1 6435.9,4527.4
  region net LOAD+: 6003.8,4986.7 5996.7,4993.8 6000,5003.7 6002.5,5013.8 6004.3,5024.1 6005.3,5034.6 6005.6,5045 6055.1,4995.5 6044.6,4995.2 6034.2,4994.2 6023.9,4992.4 6013.8,4989.9 6003.8,4986.7

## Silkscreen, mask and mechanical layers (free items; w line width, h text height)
Top Silkscreen Layer:
  text "+" at 3252.9,5096.2 h120
  text "LOAD" at 6652.9,4940.2 h120
  text "-" at 6768.9,4832.2 h120
  text "LED" at 5248.9,4688.2 h120
  text "-" at 3266.9,4586.2 h120
  text "CLK" at 5144.9,4586.2 h60
  text "VCC" at 3360.9,4550.2 h120
  text "DIO" at 4982.6,4530.2 h60
  text "+" at 6758.9,4338.2 h120
  text "POWER" at 4078.9,3970.2 h120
